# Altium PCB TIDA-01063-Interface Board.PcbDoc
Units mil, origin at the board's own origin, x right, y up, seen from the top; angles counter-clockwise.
Board outline 1968.5 x 1968.5 mil, 2 copper layers (Top Layer, Bottom Layer), stack 62 mil thick; 85 components, 32 nets, 176 pads, 89 vias.
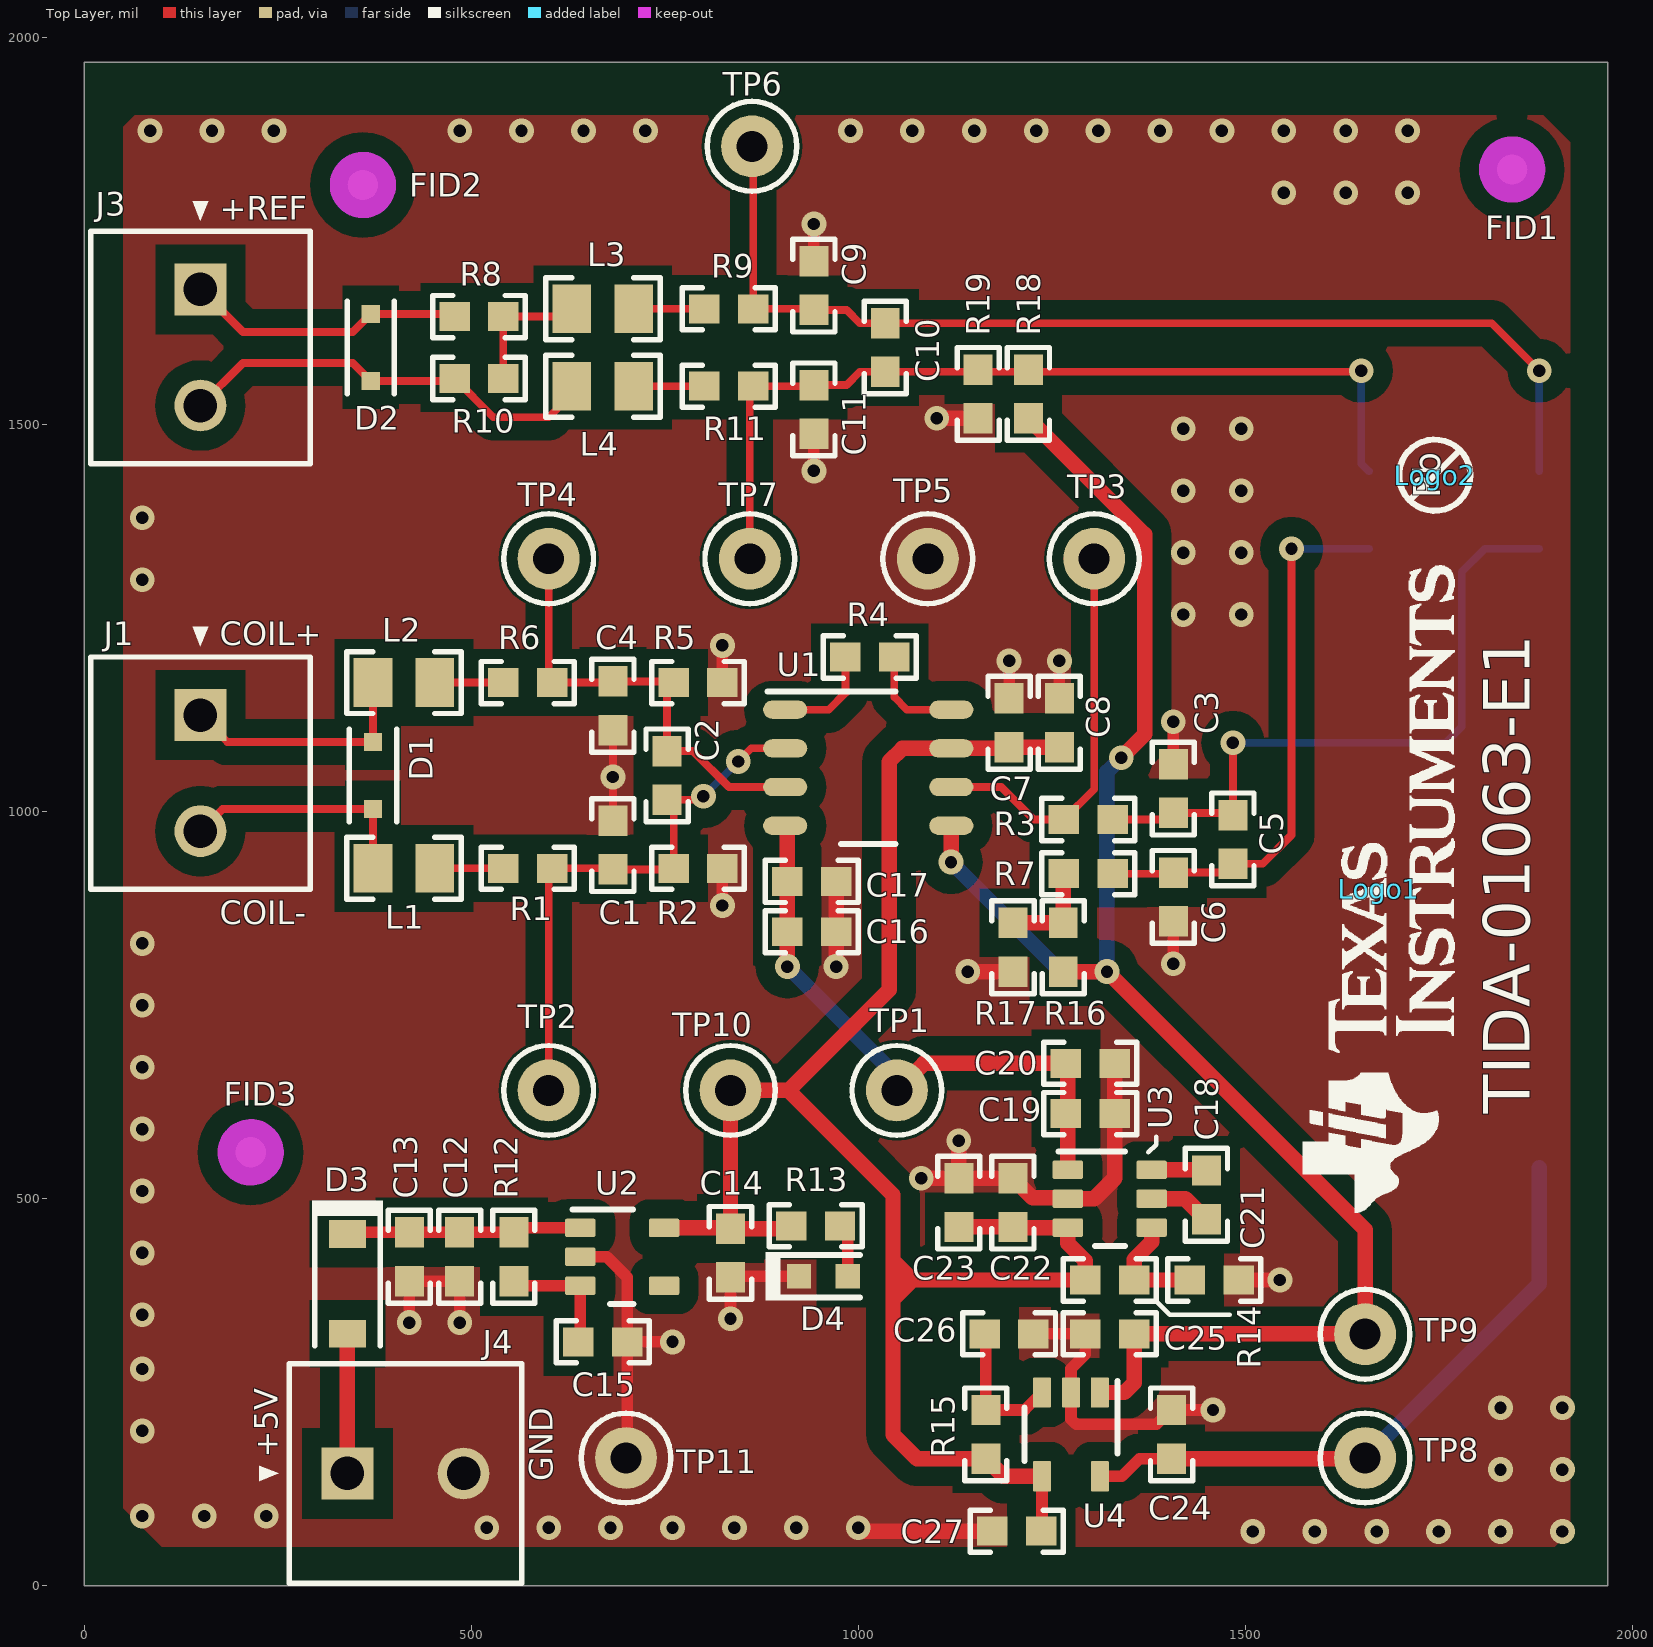
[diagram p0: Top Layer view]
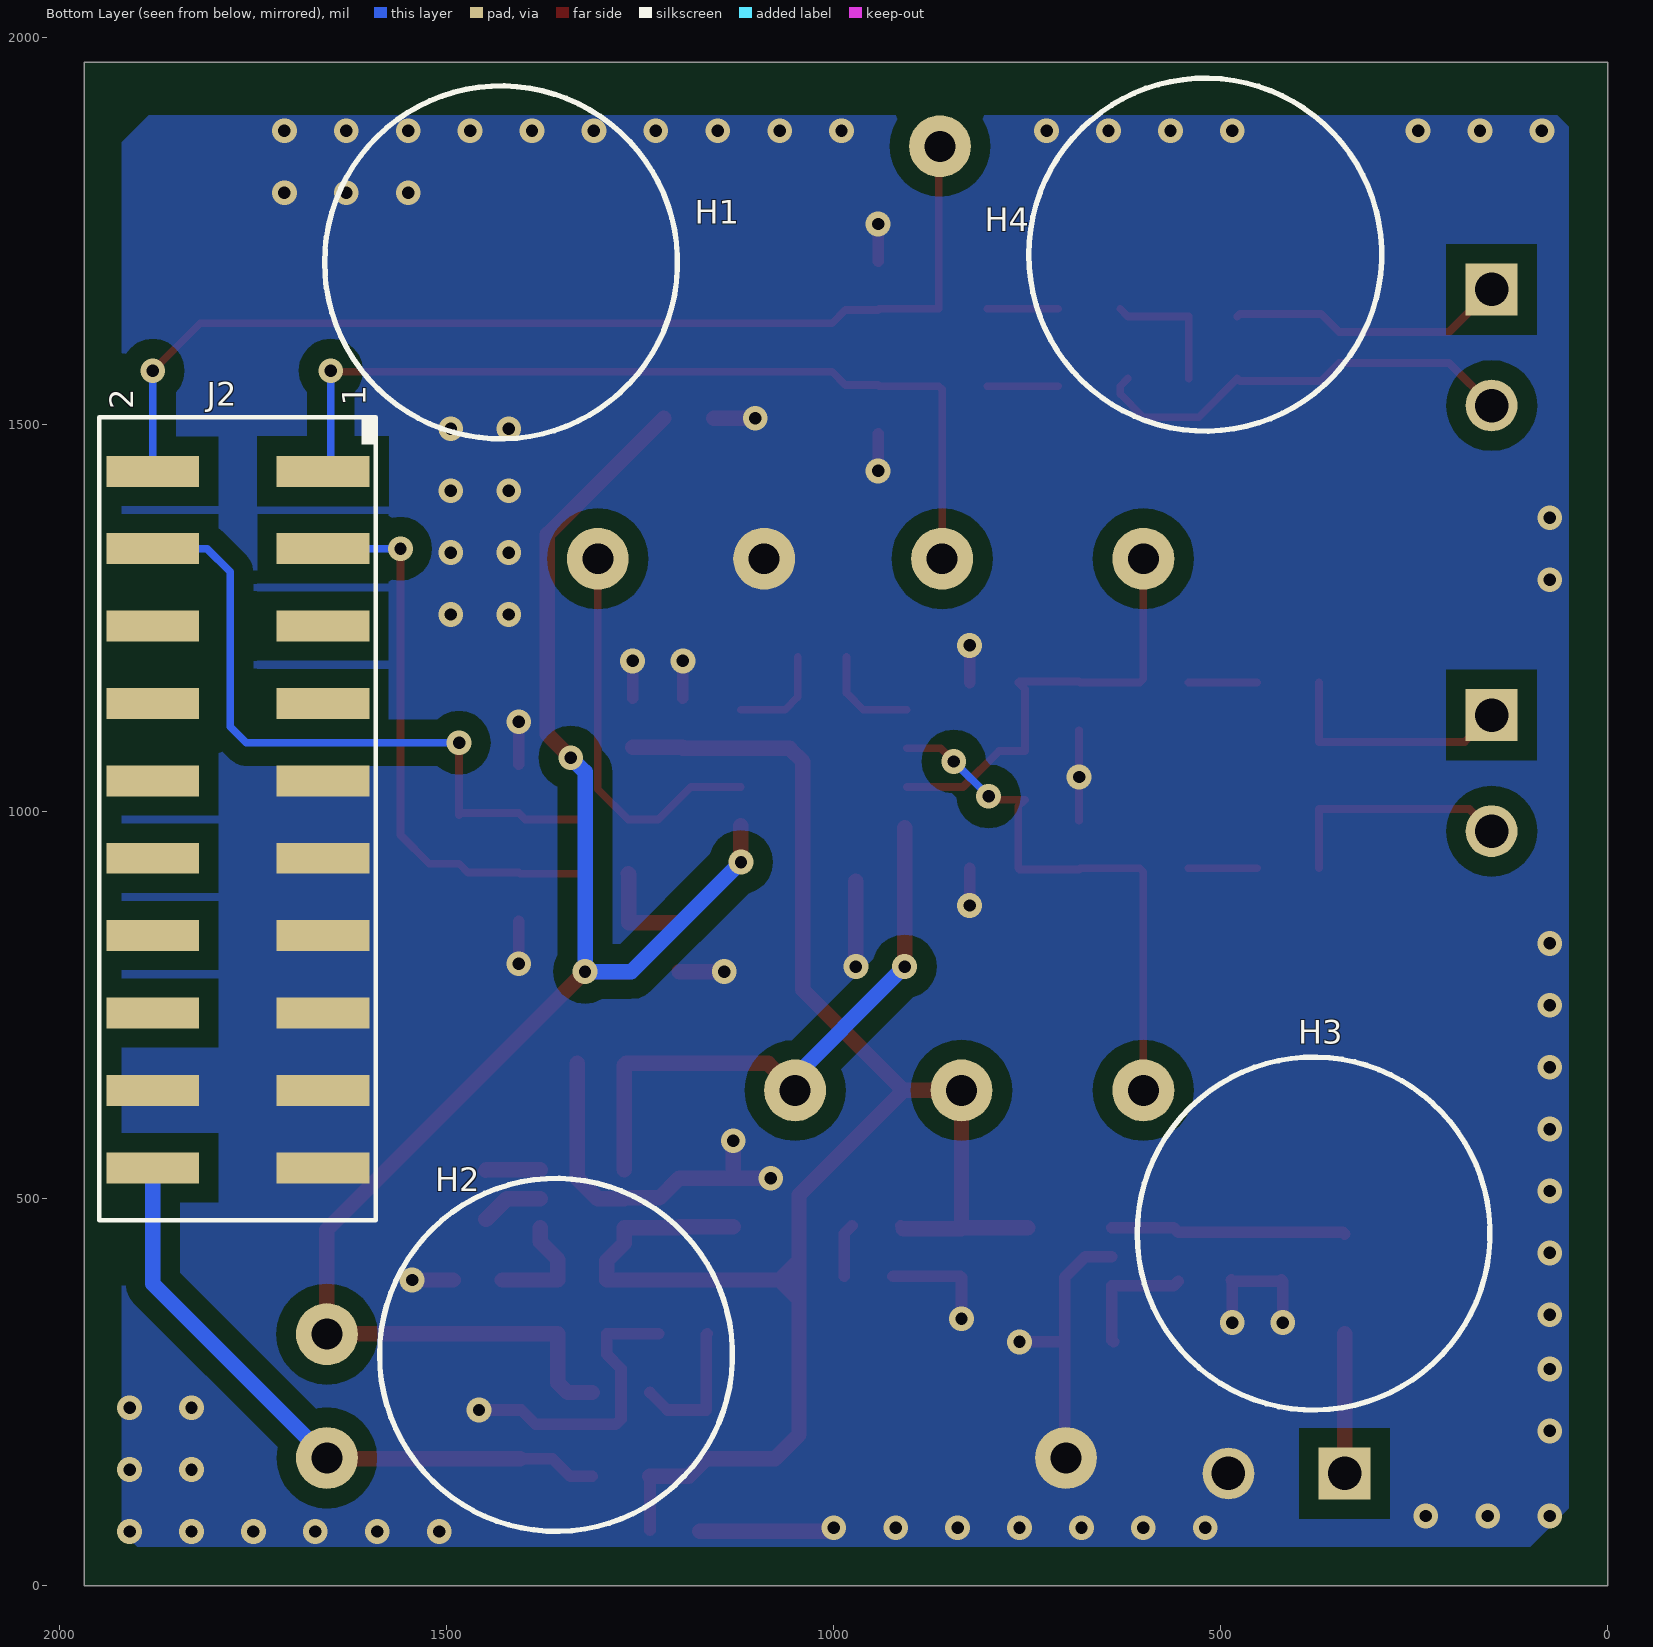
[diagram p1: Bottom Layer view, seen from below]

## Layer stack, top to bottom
Top Solder: solder mask 0.4, Solder Resist, Dk 3.5
Top Layer: signal copper 1.4
Dielectric1: core 59.2, FR-4, Dk 4.8
Bottom Layer: signal copper 1.4
Bottom Solder: solder mask 0.4, Solder Resist, Dk 3.5

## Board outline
0,0 0,1968.5 1968.5,1968.5 1968.5,0

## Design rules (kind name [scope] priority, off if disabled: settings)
AcuteAngle [All] p1: minimum=4.50000000000000E+0001 checktracksonly=FALSE
AssemblyTestPointUsage [All] p1: valid=2
Clearance Clearance_BoardEdge_MountingHoles [OnCopper and InComponentClass('Mounting Holes') vs IsKeepOut] p1: gap=40
Clearance Clearance_BoardEdge_Poly [OnCopper and InPoly vs IsKeepOut] p2: gap=25
Clearance Clearance_BoardEdge [OnCopper and Not InComponentClass('Logo') and not InComponentClass('FiducialMark') and not InRegion(1000,500,4000,800) and Not IsKeepout vs IsKeepOut] p3: gap=75
Clearance Clearance_Poly [InPolygon] p4: gap=25
Clearance [All] p5: gap=8
DiffPairsRouting [All] p1: maxlimit=100 minlimit=10 mostfreqgap=10 toplayer_minwidth=15 toplayer_maxwidth=15 toplayer_prefwidth=15 bottomlayer_minwidth=15 bottomlayer_maxwidth=15 bottomlayer_prefwidth=15 maxuncoupledlength=1000
FabricationTestPointUsage TestPointUsage [All] p1: valid=2 allowmultiple=FALSE
FabricationTestpoint Testpoint [All] p1: side=3 testpointundercomponent=TRUE minsize=40 maxsize=100 preferedsize=60 minholesize=0 maxholesize=40 preferedholesize=32 testpointgrid=1 allowsidetop=TRUE allowsidebottom=TRUE usegrid=TRUE gridtolerance=0.01
FanoutControl Fanout_LCC [IsLCC] p1: bgadir=Out bgaviamode=Centered fanoutstyle=Auto fanoutdirection=Alternating viagrid=1 // Fanout_LCC (Default Rule)
FanoutControl Fanout_BGA [IsBGA] p2: bgadir=Out bgaviamode=Centered fanoutstyle=Auto fanoutdirection=Alternating viagrid=1 // Fanout_BGA (Default Rule)
FanoutControl Fanout_Default [All] p4: bgadir=Out bgaviamode=Centered fanoutstyle=Auto fanoutdirection=Alternating viagrid=1 // Fanout_Default (Default Rule)
FanoutControl Fanout_Small [(CompPinCount < 5)] p5: bgadir=Out bgaviamode=Centered fanoutstyle=Auto fanoutdirection=OutThenIn viagrid=1 // Fanout_Small (Default Rule)
HoleSize [All] p1: absolutevalues=TRUE maxlimit=251 minlimit=8 maxpercent=80.000 minpercent=20.000
MinimumAnnularRing MinimumAnnularRing_ThermalPadVias [IsVia and InAnyComponent] p1: minimumring=5.91
MinimumAnnularRing [All] p2: minimumring=6
MinimumSolderMaskSliver MinimumSolderMaskSliver_Logo [InComponentClass('Logo') vs InComponentClass('Logo')] p1: minsoldermaskwidth=0.7
MinimumSolderMaskSliver [All] p2: minsoldermaskwidth=3.94
PlaneConnect [All] p1: planeconnectstyle=Direct reliefexpansion=10 reliefentries=4 reliefconductorwidth=10 reliefairgap=10
PolygonConnect [All] p1: connectstyle=Direct reliefconductorwidth=10 reliefentries=4 polygonreliefangle="90 Angle" airgapwidth=10
RoutingVias ThermalPadVias [IsVia and InAnyComponent] p1: holewidth=7.87 width=19.68 viastyle="Through Hole" minholewidth=7.87 minwidth=19.68 maxholewidth=12.99 maxwidth=23.62
RoutingVias [All] p2: holewidth=16 width=32 viastyle="Through Hole" minholewidth=12 minwidth=24 maxholewidth=28 maxwidth=50
SilkToBoardRegionClearance [Not ((IsComment or IsDesignator) And (Hide <> 'False')) and not InRegion(1000,500,4000,800)] p1:
SilkToSilkClearance SilkToSilkClearance_Pb-FreeLogo [(HasFootprint('Pb-Free_Overlay_Medium') OR HasFootprint('Pb-Free_Overlay_Small')) vs (HasFootprint('Pb-Free_Overlay_Medium') OR HasFootprint('Pb-Free_Overlay_Small'))] p1: silktosilkclearance=0
SilkToSilkClearance [All] p2: silktosilkclearance=4
SilkToSolderMaskClearance SilkToComonentPadClearance [IsPad and InAnycomponent] p1: minsilkscreentomaskgap=5 clearancetoexposedcopper=TRUE
SilkToSolderMaskClearance "Silk to Solder Mask Opening" [All] p2: minsilkscreentomaskgap=4 clearancetoexposedcopper=FALSE
SolderMaskExpansion [All] p1: expansion=1.97
UnpouredPolygon [All] p1: allowunpoured=FALSE
Width [All] p1: maxlimit=100 minlimit=10 preferedwidth=10 checkconnectedcopper=TRUE
15 further rules are at their usual default settings.

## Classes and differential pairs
component class AssemblyNote: ZZ1 ZZ2 ZZ3
component class FiducialMark: FID1 FID2 FID3
component class Logo: Logo1
component class TIDA-01063-BlankSheet: C1 C2 C3 C4 C5 C6 C7 C8 C9 C10 C11 C12 C13 C14 C15 C16 C17 C18 C19 C20 C21 C22 C23 C24 C25 C26 C27 D1 D2 D3 D4 J1 J2 J3 J4 L1 L2 L3 L4 R1 R2 R3 R4 R5 R6 R7 R8 R9 R10 R11 R12 R13 R14 R15 R16 R17 R18 R19 TP1 TP2 TP3 TP4 TP5 TP6 TP7 TP8 TP9 TP10 TP11 U1 U2 U3 U4
component class TIDA-01063_Hardware: !PCB1 FID1 FID2 FID3 H1 H2 H3 H4 Logo1 Logo2 ZZ1 ZZ2 ZZ3

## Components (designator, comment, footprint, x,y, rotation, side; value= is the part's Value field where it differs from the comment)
C1 "C0603X102K5RACTU" 0603 683.01,957 r270 top
C2 "06031C103JAT2A" 0603 753.01,1047 r270 top
C3 "C0805C104K1RACTU" 0603 1407.27,1030.02 r90 top
C4 "C0603X102K5RACTU" 0603 683.01,1137 r270 top
C5 "C3225X7R2A105K200AA" 0603 1484.25,964.32 r270 top
C6 "C0805C104K1RACTU" 0603 1407.27,890.02 r90 top
C7 "CGA3E2X8R1E104K080AA" 0603 1195,1115 r90 top
C8 "C1608X5R1C105K" 0603 1260,1115 r90 top
C9 "C0603X102K5RACTU" 0603 942.8,1680.02 r90 top
C10 "06031C103JAT2A" 0603 1035,1600 r270 top
C11 "C0603X102K5RACTU" 0603 942.8,1520.02 r90 top
C12 "C1608X5R1C105K" 0603 485,425 r270 top
C13 "CGA3E2X8R1E104K080AA" 0603 420,425 r270 top
C14 "C1608X5R1C105K" 0603 835,430 r270 top
C15 "CGA3E2X8R1E104K080AA" 0603 670,315 r0 top
C16 "C1608X5R1C105K" 0603 940,845 r0 top
C17 "CGA3E2X8R1E104K080AA" 0603 940,910 r0 top
C18 "C1608X5R1C105K" 0603 1450,505 r90 top
C19 "C0603C106M9PACTU" 0603 1300,610 r0 top
C20 "C0603C106M9PACTU" 0603 1300,675 r0 top
C21 "CGA3E2X8R1E104K080AA" 0603 1460,395 r0 top
C22 "C0603C106M9PACTU" 0603 1200,495 r90 top
C23 "C0603C106M9PACTU" 0603 1130,495 r90 top
C24 "CGA3E2X8R1E104K080AA" 0603 1404.96,195.5 r90 top (schematic designator C16)
C25 "CGA3E2X8R1E104K080AA" 0603 1324.96,325.5 r180 top (schematic designator C17)
C26 "CGA3E2X8R1E104K080AA" 0603 1194.96,325.5 r0 top (schematic designator C18)
C27 "CGA3E2X8R1E104K080AA" 0603 1204.96,70.5 r180 top (schematic designator C19)
D1 "CDSOD323-T03SC" SOD-323-Bi 373.01,1047 r90 top
D2 "CDSOD323-T03SC" SOD-323-Bi 370,1600 r90 top
D3 "BAT41ZFILM" SOD-123 340,390 r270 top
D4 "150060GS75000" WL-SMCW_GREEN 955,400 r0 top
FID1 "Fiducial" Fiducial10-20 1845,1830 r0 top
FID2 "Fiducial" Fiducial10-20 360,1810 r0 top
FID3 "Fiducial" Fiducial10-20 215,560 r0 top
H1 "SJ-5303 (CLEAR)" Bumpon_SJ5003Transparent 1430,1710 r180 bottom
H2 "SJ-5303 (CLEAR)" Bumpon_SJ5003Transparent 1358.96,298.23 r180 bottom
H3 "SJ-5303 (CLEAR)" Bumpon_SJ5003Transparent 380,455 r180 bottom
H4 "SJ-5303 (CLEAR)" Bumpon_SJ5003Transparent 520,1720 r180 bottom
J1 "1727010" PhoenixConact_1727010 150,1050 r270 top
J2 "SSW-110-22-F-D-VS-K" CONN_SSW-110-22-F-D-VS-K 1770,990 r90 bottom (schematic designator J?)
J3 "1727010" PhoenixConact_1727010 150,1600 r270 top
J4 "1727010" PhoenixConact_1727010 415,145 r0 top
L1 "FBMJ2125HM210NT" 0805_HV 413.01,927 r0 top
L2 "FBMJ2125HM210NT" 0805_HV 413.01,1167 r0 top
L3 "FBMJ2125HM210NT" 0805_HV 670,1650 r0 top
L4 "FBMJ2125HM210NT" 0805_HV 670,1550 r0 top
Logo1 "Texas Instruments" TI_Stacked_Overlay_Small 1672.5,900 r90 top
Logo2 "Pb-Free Symbol" Pb-Free_Overlay_Small 1745,1435 r90 top
R1 "RT0603DRE0710KL" 0603 573.01,927 r0 top
R2 "RC0603FR-07100KL" 0603 793.01,927 r0 top
R3 "CRCW06030000Z0EA" 0603 1297.27,990.02 r0 top
R4 "ERA-3AEB101V" 0603 1015,1200 r0 top
R5 "RC0603FR-07100KL" 0603 793.01,1167 r180 top
R6 "RT0603DRE0710KL" 0603 573.01,1167 r0 top
R7 "CRCW06030000Z0EA" 0603 1297.27,920.02 r0 top
R8 "RT0603DRE0710KL" 0603 510,1640 r180 top
R9 "RT0603DRE0710KL" 0603 832.8,1650.02 r0 top
R10 "RT0603DRE071KL" 0603 510,1560 r180 top
R11 "RT0603DRE0710KL" 0603 832.8,1550.02 r0 top
R12 "RC0603FR-07100KL" 0603 555,425 r90 top
R13 "RC0603FR-07390RL" 0603 945,465 r180 top
R14 "RC0603FR-07100KL" 0603 1325,395 r180 top
R15 "RC0603FR-07100KL" 0603 1164.96,195.5 r270 top (schematic designator R14)
R16 "CRCW06030000Z0EA" 0603 1265,825 r90 top
R17 "CRCW06030000Z0EA" 0603 1200,825 r270 top
R18 "CRCW06030000Z0EA" 0603 1220,1540 r90 top
R19 "CRCW06030000Z0EA" 0603 1155,1540 r270 top
TP1 "5002" Keystone5002 1050,640 r0 top
TP2 "5004" Keystone5004 600,640 r0 top
TP3 "5002" Keystone5002 1305,1327 r0 top
TP4 "5000" Keystone5000 600,1327 r0 top
TP5 "5001" Keystone5001 1090,1327 r0 top
TP6 "5000" Keystone5000 862.8,1860.02 r0 top
TP7 "5004" Keystone5004 860,1327 r0 top
TP8 "5002" Keystone5002 1655,165 r180 top
TP9 "5002" Keystone5002 1655,325 r0 top (schematic designator TP1)
TP10 "5002" Keystone5002 835,640 r180 top
TP11 "5001" Keystone5001 700,165 r0 top
U1 "INA188D" D0008A_N 1013.01,1057 r0 top
U2 "LP5907MFX-3.3/NOPB" DBV0005A_N 695,425 r0 top
U3 "LM2776DBVR" DBV0006A_N 1325,500 r0 top
U4 "REF2030AIDDCR" DDC0005A_N 1274.96,195.5 r270 top (schematic designator U3)
ZZ1 "These assemblies are ESD sensitive, ESD precautions shall be observed." AssemblyNote 5,2460 r0 top
ZZ2 "These assemblies must be clean and free from flux and all contaminants. Use of no clean flux is not acceptable." AssemblyNote 5,2370 r0 top
ZZ3 "These assemblies must comply with workmanship standards IPC-A-610 Class 2, unless otherwise specified." AssemblyNote 5,2275 r0 top

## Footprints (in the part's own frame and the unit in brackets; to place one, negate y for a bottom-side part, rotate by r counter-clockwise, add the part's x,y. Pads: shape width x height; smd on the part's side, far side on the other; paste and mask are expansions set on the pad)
0603 [mm] "0603 from SM-752 data"
  rect 1x0.95 smd: 1(-0.8,0) 2(0.8,0)
  silkscreen extent -1.52,-0.69 1.52,0.69, body extent -0.87,-0.47 0.87,0.47, height 1
0805_HV [mil] "0805 with 30mil clearance between pads"
  rect 50x63 smd: 1(-40,0) 2(40,0)
  silkscreen extent -74,-40 74,40, body extent -43,-29 43,29, height 57
AssemblyNote [mil] "Assembly Note"
Bumpon_SJ5003Transparent [mil] "3M Hemispherical Bumpon transparent"
  round 1 on Mech4: 0(0,0)
  silkscreen extent -228,-228 228,228, body extent -217,-218 219,218, height 197
CONN_SSW-110-22-F-D-VS-K [mil]
  rect 40x120 smd: 1(450,-110) 2(450,110) 3(350,-110) 4(350,110) 5(250,-110) 6(250,110) 7(150,-110) 8(150,110) 9(50,-110) 10(50,110) 11(-50,-110) 12(-50,110) 13(-150,-110) 14(-150,110) 15(-250,-110) 16(-250,110) 17(-350,-110) 18(-350,110) 19(-450,-110) 20(-450,110)
  silkscreen extent -518,-178 520,179, body extent -510,-155 500,155, height 435
D0008A_N [mm] "SOIC, 8-Leads, Body 4.9x3.9mm, Pitch 1.27mm, IPC Medium Density"
  oval 1.45x0.6 smd: 1(-2.725,1.905) 2(-2.725,0.635) 3(-2.725,-0.635) 4(-2.725,-1.905) 5(2.725,-1.905) 6(2.725,-0.635) 7(2.725,0.635) 8(2.725,1.905)
  silkscreen extent -3.3,-2.5 0.9,2.5, body extent -3,-2.45 3,2.45, height 1.63
DBV0005A_N [mm] "SOT23, 5-Leads, Body 2.9x1.6mm, Pitch 0.95mm, Lead Span 2.8mm, IPC Medium Density"
  rrect17% 1x0.6 smd: 1(-1.375,0.95) 2(-1.375,0) 3(-1.375,-0.95) 4(1.375,-0.95) 5(1.375,0.95)
  silkscreen extent -1.63,-1.55 0.38,1.55, body extent -1.42,-1.46 1.42,1.46, height 1.09
DBV0006A_N [mm] "SOT23, 6-Leads, Body 2.9x1.6mm, Pitch 0.95mm, Lead Span 2.8mm, IPC Medium Density"
  rrect17% 1x0.6 smd: 1(-1.375,0.95) 2(-1.375,0) 3(-1.375,-0.95) 4(1.375,-0.95) 5(1.375,0) 6(1.375,0.95)
  silkscreen extent -1.68,-1.55 0.5,1.55, body extent -1.42,-1.46 1.42,1.46, height 1.12
DDC0005A_N [mm]
  rrect17% 1x0.6 smd: 1(-1.375,0.95) 2(-1.375,0) 3(-1.375,-0.95) 4(1.375,-0.95) 5(1.375,0.95)
  silkscreen extent -1.75,-1.52 0.88,1.53, body extent -1.41,-1.45 1.41,1.45, height 1.1
Fiducial10-20 [mm]
  round 1 smd mask+0.5: 1(0,0)
  Top Layer keep-out circle w1.178: c0,0 r0.5
Keystone5000 [mil] "For Keystone 500x miniature loop terminals"
  round 80 hole 40: 1(0,0)
  silkscreen extent -58,-58 58,58, body extent -49,-49 49,49, height 182
Keystone5001 [mil] "For Keystone 500x miniature loop terminals"
  round 80 hole 40: 1(0,0)
  silkscreen extent -58,-58 58,58, body extent -49,-49 49,49, height 182
Keystone5002 [mil] "For Keystone 500x miniature loop terminals"
  round 80 hole 40: 1(0,0)
  silkscreen extent -58,-58 58,58, body extent -49,-49 49,49, height 182
Keystone5004 [mil] "For Keystone 500x miniature loop terminals"
  round 80 hole 40: 1(0,0)
  silkscreen extent -58,-58 58,58, body extent -49,-49 49,49, height 182
Pb-Free_Overlay_Small [mil]
  silkscreen extent -46,-46 46,46
PhoenixConact_1727010 [mm]
  rect 1.7x1.7 hole 1.1: 1(-1.905,0)
  round 1.7 hole 1.1: 2(1.905,0)
  silkscreen extent -4.8,-3.6 3.81,3.6, body extent -3.81,-3.6 3.81,3.7, height 8.52
SOD-123 [mm] "On Semi recommended land pattern"
  rect 0.915x1.22 smd: 1(-1.637,0) 2(1.637,0)
  silkscreen extent -2.74,-1.17 2.03,1.17, body extent -1.93,-0.9 1.93,0.9, height 1.35
SOD-323-Bi [mm] "SOD323, 2-Leads, Body 1.9x1.45mm, No Polarity Mark"
  rect 0.6x0.6 smd paste-0.05: 1(-1.1,0) 2(1.1,0)
  silkscreen extent -1.53,-0.77 1.53,0.77, body extent -1.27,-0.65 1.27,0.65, height 1.02
TI_Stacked_Overlay_Small [mil]
  silkscreen extent -418,-98 418,98
WL-SMCW_GREEN [mm] "WURTH"
  rect 0.8x0.8 smd: 1(-0.8,0) 2(0.8,0)
  silkscreen extent -1.9,-0.8 1.2,0.8, body extent -0.85,-0.45 0.85,0.45, height 0.8

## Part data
C1 C4 C9 C11: "CAP, CERM, 1000 pF, 50 V, +/- 10%, X7R, 0603"
C2 C10: "CAP, CERM, 0.01 µF, 100 V, +/- 5%, X7R, 0603"
C3 C6: library part C0603C104J3RACTU, "CAP, CERM, 0.1 µF, 25 V, +/- 5%, X7R, 0603"
C5: library part C1608X5R0J105K, "CAP, CERM, 1 µF, 6.3 V, +/- 10%, X5R, 0603"
C7 C13 C15 C17 C21 C24 C25 C26 C27: "CAP, CERM, 0.1 µF, 25 V, +/- 10%, X8R, AEC-Q200 Grade 0, 0603"
C8 C12 C14 C16 C18: "CAP, CERM, 1 µF, 16 V, +/- 10%, X5R, 0603"
C19 C20 C22 C23: "CAP, CERM, 10 µF, 6.3 V, +/- 20%, X5R, 0603"
D1 D2: "Diode, TVS, Bi, 3.3 V, 400 W, SOD323, 2-Leads, Body 1.9x1.45mm, No Polarity Mark"
D3: "Diode, Schottky, 100 V, 0.2 A, SOD-123"
D4: "LED, Green, SMD"
FID1 FID2 FID3: "Fiducial mark.  There is nothing to buy or mount."
H1 H2 H3 H4: "Bumpon, Hemisphere, 0.44 X 0.20, Clear"
J1 J3 J4: "Conn Term Block, 2POS, 3.81mm, TH"
J2: "Connector, Receptacle, 100mil, 10x2, Gold plated, SMD"
L1 L2 L3 L4: "Ferrite Bead, 21 ohm @ 100 MHz, 6 A, 0805"
Logo1: library part TI_Logo, "Texas Instrument Corporate Signature"
Logo2: library part Pb-Free
R1 R6 R8 R9 R11: "RES, 10.0 k, 0.5%, 0.1 W, 0603"
R2 R5 R12 R14 R15: "RES, 100 k, 1%, 0.1 W, 0603"
R3 R7 R16 R17 R18 R19: "RES, 0, 5%, 0.1 W, 0603"
R4: "RES, 100, 0.1%, 0.1 W, AEC-Q200 Grade 0, 0603"
R10: "RES, 1.00 k, 0.5%, 0.1 W, 0603"
R13: "RES, 390, 1%, 0.1 W, 0603"
TP1 TP3 TP8 TP9 TP10: "Test Point, Miniature, White, TH"
TP2 TP7: "Test Point, Miniature, Yellow, TH"
TP4 TP6: "Test Point, Miniature, Red, TH"
TP5 TP11: "Test Point, Miniature, Black, TH"
U1: "INA188 Precision, Zero-Drift, Rail-to-Rail Out, High Voltage Instrumentation Amplifier, D0008A"
U2: "ULTRA LOW-NOISE, 250-mA LINEAR REGULATOR FOR RF AND ANALOG CIRCUITS REQUIRES NO BYPASS CAPACITOR, DBV0005A"
U3: "Switched Capacitor Inverter, DBV0006A"
U4: "Low-Drift, Low-Power, Dual-Output, VREF and VREF / 2 Voltage References, 3.0V, DDC0005A"
ZZ1 ZZ2 ZZ3: library part AssemblyNote

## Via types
v1: diameter 32, hole 16, Top Layer to Bottom Layer, 89 vias

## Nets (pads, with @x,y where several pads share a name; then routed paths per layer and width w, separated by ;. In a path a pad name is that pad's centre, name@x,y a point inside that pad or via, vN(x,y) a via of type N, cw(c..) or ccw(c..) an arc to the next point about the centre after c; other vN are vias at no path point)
+3.3V: C7.1 C8.1 C14.1 C22.1 C23.1 C27.1 R13.2 R14.2 R15.2 TP10.1 U1.7 U2.5 U3.3 U4.4 | length 2447.9
  Top Layer w15: R13.2@910,461.5 R13.2 ; C27.1@1237.56,71.6 U4.4
  Top Layer w20: U2.5 C14.1@834.09,462.4 ; R13.2@910,461.5 C14.1 C14.1@834.09,462.4 ; 1045,370 1070,395 1045,420 ; C23.1 C22.1 1200.91,462.6 U3.3 1270.87,442.33 1293.5,419.7 R14.2 1045,395 ; C7.1@1195,1082 U1.7 1057,1082 1040,1065 1040,770 910,640 ; C7.1 C8.1 ; U4.4 1187.6,141.37 R15.2 1076,164 1045,195 1045,395 ; C14.1@834.09,462.4 835,463.31 TP10.1 910,640 ; 910,640 1045,505 1045,395
-3.3V: C16.1 C17.1 C19.1 C20.1 TP1.1 U1.4 U3.1 | length 777.1
  Top Layer w20: v1(908.5,800) C16.1 C17.1 U1.4@908.5,979.23 ; TP1.1 1085,675 C20.1 1270.87,672.64 U3.1
  Bottom Layer w20: v1(908.5,800) TP1.1@1068.5,640
AN0+: C9.1 C10.1 J2.2 R9.2 TP6.1 | length 1389.5
  Top Layer w10: TP6.1 864.3,1858.52 R9.2 941.3,1650.02 C9.1 985,1648.52 1002.03,1631.5 C10.1 1818.5,1631.5 v1(1880,1570)
  Bottom Layer w10: J2.2 v1(1880,1570)
AN0-: C10.2 C11.2 J2.1 R11.2 R18.2 R19.1 TP7.1 | length 1779.3
  Top Layer w10: TP7.1 860,1545.72 R11.2 941.3,1550.02 C11.2 985,1551.51 1001.99,1568.5 C10.2 1648.5,1568.5 C10.2@1022.8,1568.52 ; TP7.1@864.3,1324.3 TP7.1@864.3,1327
  Bottom Layer w10: v1(1650,1570) 1650,1450 J2.1
AN1+: C3.1 C5.1 J2.4 R3.2 | length 870.4
  Top Layer w10: R3.2 1398.76,990.02 C3.1 1481.54,998.52 C5.1 v1(1484.25,1089.32)
  Bottom Layer w10: v1(1484.25,1089.32) 1759.32,1089.32 1780,1110 1780,1310 1810,1340 J2.4
AN1-: C5.2 C6.2 J2.3 R7.2 | length 721.9
  Top Layer w10: R7.2 1405.77,920.02 C6.2 1472.95,921.51 C5.2 1522.76,932.82 1560,970.06 v1(1560,1340)
  Bottom Layer w10: v1(1560,1340) J2.3
GND: C1.1 C3.2 C4.2 C6.1 C7.2 C8.2 C9.2 C11.1 C12.2 C13.2 C14.2 C15.2 C16.2 C17.2 C19.2 C20.2 C21.2 C22.2 C23.2 C24.2 C25.2 C26.2 C27.2 D4.1 J2.9 J2.11 J2.13 J2.15 J2.17 J2.18 J2.19 J4.2 R2.2 R5.1 R17.2 R19.2 TP5.1 TP11.1 U2.2 U3.2 U4.2 | length 2496.1
  Top Layer w10: C1.1 v1(683.01,1045) C4.2
  Top Layer w15: v1(420,340) C13.2 ; C13.2@421.5,395 C13.2 ; v1(485,340) C12.2 ; C12.2@486.5,395 C12.2 ; U2.2 675,425 701.5,398.5 C15.2 ; TP11.1@701.5,166.5 C15.2 ; v1(760,315) C15.2 ; v1(824.51,879) R2.2 ; R5.1 v1(824.51,1215) ; v1(835,345) C14.2 836.5,400 D4.1 ; v1(942.8,1440.52) C11.1 ; C9.2 v1(942.8,1759.51) ; C7.2 v1(1195,1195) ; C26.2 C25.2 1293.46,299 1274.96,280.5 U4.2 1274.96,215.19 1281.78,208.37 1385.48,208.37 1404.11,227 C24.2 v1(1458.46,227) ; C8.2 v1(1260,1195) ; v1(1407.27,803.73) C6.1 ; C3.2 v1(1407.27,1116.3) ; C13.2 C12.2
  Top Layer w20: v1(971.5,800) C16.2 C17.2 ; v1(1000,75) 1004.5,70.5 C27.2 ; v1(1081.5,526.5) C23.2 ; v1(1101.5,1508.5) R19.2 ; v1(1130,575) C23.2 ; v1(1141.5,793.5) R17.2 ; C20.2 C19.2 1331.5,526.5 1305,500 U3.2 1270.87,501.19 1225.31,501.19 C22.2 C23.2 ; C21.2 v1(1545,395)
  other v1: 1510,70 1590,70 1670,70 1750,70 1830,70 1910,70 520,75 600,75 680,75 760,75 840,75 920,75 75,90 155,90 235,90 1830,150 1910,150 75,200 1830,230 1910,230 75,280 75,350 75,430 75,510 75,590 75,670 75,750 75,830 1420,1255 1495,1255 75,1300 1420,1335 1495,1335 75,1380 1420,1415 1495,1415 1420,1495 1495,1495 1550,1800 1630,1800 1710,1800 85,1880 165,1880 245,1880 485,1880 565,1880 645,1880 725,1880 990,1880 1070,1880 1150,1880 1230,1880 1310,1880 1390,1880 1470,1880 1550,1880 1630,1880 1710,1880
NetC1_2: C1.2 C2.2 R1.2 R2.1 TP2.1 U1.2 | length 719.4
  Top Layer w10: TP2.1 600,922.49 R1.2 681.52,927 C1.2 760.02,925.5 R2.1 761.52,1007 C2.2 795.5,1015.5 v1(800,1020) ; v1(845,1065) 862,1082 U1.2
  Bottom Layer w10: v1(800,1020) v1(845,1065)
NetC2_1: C2.1 C4.1 R5.2 R6.2 TP4.1 U1.3 | length 584.1
  Top Layer w10: TP4.1 600,1171.51 R6.2 681.52,1167 C4.1 760.02,1168.5 R5.2 753.01,1158.5 C2.1 786.5,1078.5 833,1032 U1.3
NetC12_1: C12.1 C13.1 D3.1 R12.2 U2.1 | length 304.2
  Top Layer w15: D3.1 342.03,456.5 C13.1 C12.1 R12.2 560.91,462.4 U2.1
NetC15_1: C15.1 R12.1 U2.3 | length 161.9
  Top Layer w15: R12.1 560.91,387.6 U2.3 640.87,317.36 C15.1
NetC18_1: C18.1 U3.5 | length 81.8
  Top Layer w20: U3.5 1422.65,500 1449.15,473.5 C18.1
NetC18_2: C18.2 U3.6 | length 71.2
  Top Layer w20: U3.6 1449.09,537.4 C18.2
NetC21_1: C21.1 R14.1 U3.4 | length 149
  Top Layer w20: U3.4 1379.13,444.13 1356.5,421.5 R14.1 C21.1
NetC26_1: C26.1 R15.1 U4.3 | length 181.1
  Top Layer w15: C26.1 1164.96,324 R15.1 1214.92,227 U4.3
NetD1_1: D1.1 J1.2 L1.1 | length 330.1
  Top Layer w10: J1.2@150,965 165,965 J1.2@167.5,967.5 ; J1.2 178.69,1003.69 D1.1 L1.1
NetD1_2: D1.2 J1.1 L2.1 | length 321.1
  Top Layer w10: J1.1 184.69,1090.31 D1.2 L2.1 ; J1.1@150,1135 J1.1@155,1130
NetD2_1: D2.1 J3.2 L4.1 R10.2 | length 571.1
  Top Layer w10: J3.2 205,1580 346.69,1580 D2.1 475.2,1556.69 R10.2 528.5,1510 600,1510 630,1540 L4.1 L4.1@620,1560
NetD2_2: D2.2 J3.1 R8.2 | length 362.3
  Top Layer w10: J3.1 205,1620 346.69,1620 D2.2 475.2,1643.31 R8.2
NetD3_2: D3.2 J4.1 | length 180.5
  Top Layer w20: J4.1 D3.2
NetD4_2: D4.2 R13.1 | length 69.1
  Top Layer w15: R13.1 986.5,455 D4.2
NetL1_2: L1.2 R1.1 | length 88.5
  Top Layer w10: L1.2 R1.1
NetL2_2: L2.2 R6.1 | length 88.5
  Top Layer w10: L2.2 R6.1
NetL3_1: L3.1 R8.1 R10.1 | length 172.6
  Top Layer w10: R10.1 R8.1 620,1640 L3.1
NetL3_2: L3.2 R9.1 | length 91.3
  Top Layer w10: L3.2 R9.1
NetL4_2: L4.2 R11.1 | length 91.3
  Top Layer w10: L4.2 R11.1
NetR4_1: R4.1 U1.1 | length 133.2
  Top Layer w10: U1.1 962,1132 983.5,1153.5 R4.1
NetR4_2: R4.2 U1.8 | length 132.1
  Top Layer w10: R4.2 1046.5,1148.5 1063,1132 U1.8
NetR7_1: R7.1 R16.2 R17.1 | length 128.8
  Top Layer w20: R17.1 R16.2 1265,919.25 R7.1
VBIAS: C25.1 R16.1 R18.1 TP9.1 U1.5 U4.1 | length 2178.4
  Top Layer w20: v1(1120,935) 1120.3,935.3 U1.5 ; R18.1 1370,1358.5 1370,1100 v1(1340,1070) ; R16.1 v1(1321.5,793.5) 1655,460 TP9.1 ; U4.1 1344.09,249.63 1356.46,262 C25.1 TP9.1@1654.5,325.5
  Bottom Layer w20: v1(1120,935) 1261.5,793.5 v1(1321.5,793.5) 1321.5,1051.5 v1(1340,1070)
VIN: R3.1 TP3.1 U1.6 | length 518.2
  Top Layer w10: U1.6 1185,1032 1226.98,990.02 R3.1 1305,1029.25 TP3.1 ; TP3.1@1270,1327 TP3.1@1271.52,1325.48
VREF: C24.1 J2.20 TP8.1 U4.5 | length 820.6
  Top Layer w15: U4.5 1340.83,141.37 1363.46,164 C24.1
  Top Layer w20: C24.1 1654,164 TP8.1
  Bottom Layer w20: TP8.1 1880,390 J2.20
pads on no net: FID1.1 FID2.1 FID3.1 H1.0 H2.0 H3.0 H4.0 J2.5 J2.6 J2.7 J2.8 J2.10 J2.12 J2.14 J2.16 U2.4

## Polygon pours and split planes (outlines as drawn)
GND on Bottom Layer "Bottom Layer-No Net 1" (solid, remove dead copper, pour order 4): 50,1885 50,100 100,50 1900,50 1920,70 1920,130 1920,1865 1885,1900 65,1900
GND on Top Layer "Bottom Layer-No Net 1" (solid, remove dead copper, pour order 3): 50,1885 50,100 100,50 1900,50 1920,70 1920,130 1920,1865 1885,1900 65,1900

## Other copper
Top Layer:
  text "Top Layer" at -1381,-4374.49 h60
Bottom Layer:
  text ".Layer_Name" at -1381,-4374.49 h60

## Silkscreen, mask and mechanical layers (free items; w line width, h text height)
Top Overlay:
  lines w6: 1375,560 1385,570 1385,580 ; 1384.98,367.73 1402.72,350 1480,350
  text "+REF" at 175,1765 h30
  text "COIL+" at 175,1215 h30
  text "COIL-" at 175,855 h30
  text "TIDA-01063-E1" at 1867.5,610 h60 r90
  text "+5V" at 250,165 h30 r90
  text "GND" at 605,135 h30 r90
  text "TOP Overlay" at -1381,-4374.49 h60
Bottom Overlay:
  text ".Layer_Name" at -1381,-4374.49 h60
Top Paste:
  text ".Layer_Name" at -1381,-4374.49 h60
Bottom Paste:
  text ".Layer_Name" at -1381,-4374.49 h60
Top Solder:
  text ".Layer_Name" at -1381,-4374.49 h60
  text ".Layer_Name" at -1381,-4374.49 h60
Bottom Solder:
  text ".Layer_Name" at -1381,-4374.49 h60
M1 Board Outline:
  the board outline again, w7
M2 Board Dimensions:
  rectangle: -1833,-3916 -1458,-3791
  rectangle: -1958,-3791 -1833,-3666
  lines w7: -1958,-3791 -958,-3791 ; -1833,-3916 -1833,-3666 ; -1708,-3916 -1708,-3666 ; -1458,-3916 -1458,-3666 ; -1208,-3916 -1208,-3666 ; -1958,-3916 -1958,-3666 -958,-3666 -958,-3916 -1958,-3916
M3 3D STEP Top:
  text ".Layer_Name" at -1381,-4374.49 h60
M4 3D STEP Bottom:
  text ".Layer_Name" at -1381,-4374.49 h60
M5 Assembly Top:
  circle w10: c1310,215 r5
  circle w10: c615,462.4 r12.44
  lines w10: -2250,-4446.17 4350,-4446.17 ; -2250,-4242.83 4352,-4242.83 ; -2250,-4039.5 -2250,-4649.5 1755,-4649.5 4352,-4649.5 4352,-4039.5 -2249.5,-4039.5 -2249.5,-4649.5 -674,-4649.5 ; 215,-4649.5 215,-4039.5 ; 1482,-4242.83 1482,-4039.5 ; 2322,-4242.83 2322,-4039.5 ; 2944,-4656 2944,-4453.17
  text "COMPONENTS MARKED 'DNP' SHOULD NOT BE POPULATED." at -804.5,-3834.5 h30
  text "ASSEMBLY VARIANT:" at -805,-3950 h30
  text ".VariantName" at 231,-3950 h30
  text "PCB VIEWED FROM TOP SIDE" at -2186.5,-4171.67 h30
  text "BOARD #:" at 290,-4171.67 h30
  text ".PRJ_Number" at 835.5,-4171.67 h30
  text "REV:" at 1680,-4171.67 h30
  text ".PCB_Rev" at 1971.5,-4171.67 h30
  text "SVN REV:" at 2518,-4171.67 h30
  text ".VersionControl_RevNumber" at 3024,-4171.67 h30
  text "M5 Assembly Top" at -1360,-4365 h30
  text "TIDA-01063" at 740,-4370 h30
  text "LAYER NAME =" at -2183.5,-4373.49 h30
  text "TID #:" at 290,-4375 h30
  text "PLOT NAME =" at -2186.5,-4580.34 h30
  text ".plot_File_Name" at -1381,-4580.34 h30
  text "GENERATED    :" at 292,-4580.34 h30
  text ".Print_Date" at 1161.5,-4580.34 h30
  text ".Print_Time" at 1890.5,-4580.34 h30
  text "TEXAS INSTRUMENTS" at 3155,-4580.34 h30
M6 Assembly Bottom:
  lines w10: -2250.5,-4243.33 4351.5,-4243.33 ; -2248.5,-4446.67 4351.5,-4446.67 ; -842.5,-4656.5 -842.5,-4453.67 ; -220.5,-4243.33 -220.5,-4040 ; 619.5,-4243.33 619.5,-4040 ; 1886.5,-4650 1886.5,-4040 ; 2775.5,-4650 4351,-4650 4351,-4040 -2250.5,-4040 -2250.5,-4650 346.5,-4650 4351.5,-4650 4351.5,-4040
  text "COMPONENTS MARKED 'DNP' SHOULD NOT BE POPULATED." at 4144,-3834 h30
  text ".VariantName" at 3100,-3950 h30
  text "ASSEMBLY VARIANT:" at 4139,-3950 h30
  text ".VersionControl_RevNumber" at -922.5,-4172.17 h30
  text "SVN REV:" at -416.5,-4172.17 h30
  text ".PCB_Rev" at 130,-4172.17 h30
  text "REV:" at 421.5,-4172.17 h30
  text ".PRJ_Number" at 1266,-4172.17 h30
  text "BOARD #:" at 1811.5,-4172.17 h30
  text "PCB VIEWED FROM BOTTOM SIDE" at 4288,-4172.17 h30
  text "M6 Assembly Bottom" at 3455,-4370 h30
  text "TIDA-01063" at 1266,-4375.5 h30
  text "TID #:" at 1811.5,-4375.5 h30
  text "LAYER NAME =" at 4278.5,-4378.49 h30
  text "TEXAS INSTRUMENTS" at -1053.5,-4580.84 h30
  text ".Print_Time" at 211,-4580.84 h30
  text ".Print_Date" at 940,-4580.84 h30
  text "GENERATED    :" at 1809.5,-4580.84 h30
  text ".plot_File_Name" at 3482.5,-4580.84 h30
  text "PLOT NAME =" at 4288,-4580.84 h30
M9 Title Sheet:
  drawing of 58 lines, arcs and shapes, not listed
  text "1" at -1218.16,4520.5 h70
  text "2" at 1277.5,4520.5 h70
  text "3" at 3766.84,4520.5 h70
  text "4" at 6273.51,4520.5 h70
  text "5" at 8772.5,4520.5 h70
  text "6" at 11277.5,4520.5 h70
  text "A" at -2374.5,3377.5 h70
  text "A" at 12425.5,3377.5 h70
  text "B" at -2374.5,997.5 h70
  text "B" at 12425.5,997.5 h70
  text "C" at -2374.5,-1377.5 h70
  text "C" at 12425.5,-1377.5 h70
  text "PROJECT TITLE:" at 9385.5,-3238.5 h45
  text "TIDA-01063" at 9435.5,-3371.83 h70
  text "DESIGNED FOR:" at 9385.5,-3539.5 h45
  text "Current Sensing using PCB Rogowski Coil" at 9435.5,-3679.5 h70
  text "D" at -2374.5,-3747.5 h70
  text "D" at 12425.5,-3747.5 h70
  text "FILE NAME:" at 9385.5,-3839.5 h45
  text "TIDA-01063-Interface Board" at 9435.5,-3959.5 h70
  text "Texas Instruments (TI) and/or its licensors do not warrant the accuracy or completeness of this specification" at 4416,-4121.34 h45
  text "ENGINEER:" at 9385.5,-4129.5 h45
  text "LAYOUT BY:" at 10890.5,-4129.5 h45
  text "or any information contained therein. TI and/or its licensors do not warrant that this design will meet" at 4371.01,-4234 h45
  text "Srinivasan Iyer" at 9435.5,-4284.49 h70
  text "Avinash N" at 10941,-4284.49 h70
  text "the specifications, will be suitable for your application or fit for any particular purpose, or will operate in" at 4371.01,-4346.67 h45
  text "ALTIUM DESIGNER VERSION:" at 10890.5,-4439.5 h45
  text "an implementation. TI and/or its licensors do not warrant that the design is production worthy. You should" at 4371.01,-4459.33 h45
  text "completely validate and test your design implementation to confirm the system functionality for your application." at 4416,-4572 h45
  text ".print_Scale" at 9435.5,-4572.83 h70
  text ".Application_BuildNumber" at 10941,-4572.83 h70
  text "1" at -1218.16,-4779.5 h70
  text "2" at 1277.5,-4779.5 h70
  text "3" at 3766.84,-4779.5 h70
  text "4" at 6273.51,-4779.5 h70
  text "5" at 8772.5,-4779.5 h70
  text "6" at 11277.5,-4779.5 h70
M10 Fab Notes:
  drawing of 228 lines, arcs and shapes, not listed
  text "DESIGN INFORMATION" at 10423.02,3294 h60
  text "(REFER ALSO ARRAY/PANEL PROFILING INFORMATION)" at 10061.46,3132.29 h60
  text "BOARD SIZE" at 9375.46,3128 h60
  text "50MM" at 9837.78,3000.18 h60
  text "X" at 10343.46,3000.18 h60
  text "50MM" at 10574.78,3000.18 h60
  text "Number of Layers :" at 9778.46,2803 h60
  text "2" at 10873.27,2793 h60
  text "MIN. TRACK WIDTH:" at 9778.46,2664 h60
  text "10" at 10874.7,2664 h60
  text "MIL" at 11029.46,2664 h60
  text "8.9" at 10833.1,2548.82 h60
  text "MIN. CLEARANCE:" at 9778.46,2532 h60
  text "MIL" at 11029.46,2532 h60
  text "16" at 10845.28,2408.9 h60
  text "MIN. VIA DRILL SIZE:" at 9778.46,2400 h60
  text "MIL" at 11029.46,2400 h60
  text "8 MIL" at 10473.46,2258.29 h60
  text "MINIMUM ANNULAR RING" at 9449.23,2254 h60
  text "EXTERNAL" at 11181.46,2254 h60
  text "PER" at 9649.23,2136 h60
  text "IPC-D-275 CLASS 2 LEVEL C" at 9869.23,2136 h60
  text "MIL, HOLES" at 11357.46,2023.71 h60
  text "+/-" at 10965,2023 h60
  text "+/-" at 11819,2023 h60
  text "REGISTRATION TOLERANCES:" at 9449.23,2018 h60
  text "METAL" at 10649,2018 h60
  text "5" at 11225.2,2018 h60
  text "3" at 12058.2,2018 h60
  text "MIL" at 12174.46,2018 h60
  text "MATERIAL:" at 9374.46,1808.54 h60
  text "FR-4 High Tg" at 10360.9,1668.21 h60
  text "FR-408" at 9795.46,1659.64 h60
  text "X" at 10202,1660 h60
  text "OTHER" at 11283.46,1659.64 h60
  text "63 MIL (1.6mm) +/-10%" at 10115.56,1496.92 h60
  text "THICKNESS:" at 9449.23,1492.64 h60
  text "X" at 9987.4,1492.64 h60
  text "OTHER" at 11400.46,1492.64 h60
  text "TOLERANCE:" at 9449.23,1334.64 h60
  text "X" at 10288.53,1334.64 h60
  text "ANSI IPC-6012 TYPE 3 CLASS 2" at 10475.48,1334.64 h60
  text "OTHER +/-" at 10475.46,1178.64 h60
  text "BOW & TWIST:" at 9449.23,1021.64 h60
  text "X" at 10288.53,1021.64 h60
  text "ANSI IPC-6012 TYPE 3 CLASS 2" at 10475.48,1021.64 h60
  text "OTHER +/-" at 10475.46,863.13 h60
  text "COPPER THICKNESS (FINISHED):" at 9374.46,727.64 h60
  text "1.4MIL (1oz)" at 10254.46,574.92 h60
  text "2MIL (1.4oz)" at 11021.46,574.92 h60
  text "2.8MIL (2oz)" at 11748.46,574.92 h60
  text "OUTER:" at 9731.46,570.64 h60
  text "X" at 10126,570 h60
  text "1.4MIL (1oz)" at 10254.46,417.92 h60
  text "2.8MIL (2oz)" at 11021.46,417.92 h60
  text "N/A" at 11748,418.29 h60
  text "INNER SIGNAL:" at 9442.38,413.64 h60
  text "X" at 11621,410 h60
  text "DRILLING:" at 9374.46,274.64 h60
  text "REFERENCE:" at 9449.23,157.64 h60
  text "X" at 10097.46,157.64 h60
  text "AS SHOWN" at 10284.46,157.64 h60
  text "X" at 10998.46,157.64 h60
  text "NC_DRILL FILES" at 11135.46,157.64 h60
  text "PTH MIN COPPER THICKNESS:" at 9449.23,-0.36 h60
  text "X" at 10799.46,-0.36 h60
  text "1MIL" at 10936.46,-0.36 h60
  text "OTHER" at 11433.46,-0.36 h60
  text "BOARD FINISH:" at 9374.46,-159.36 h60
  text "SILKSCREEN:" at 9529.68,-277.36 h60
  text "X" at 10478.46,-277.36 h60
  text "TOP" at 10604.46,-277.36 h60
  text "X" at 10988.46,-277.36 h60
  text "BOTTOM" at 11115.46,-277.36 h60
  text "SILKSCREEN COLOR:" at 9529.68,-444.36 h60
  text "X" at 10477.42,-444.36 h60
  text "WHITE" at 10604.46,-444.36 h60
  text "OTHER" at 11115.46,-444.36 h60
  text "SOLDER RESIST COLOR:" at 9529.68,-614.36 h60
  text "X" at 10097.42,-773.56 h60
  text "GREEN" at 10224.46,-773.56 h60
  text "BLUE" at 10815.46,-773.56 h60
  text "OTHER" at 11353.46,-773.56 h60
  text "IMMERSION GOLD (ENIG)" at 10435.46,-962.08 h60
  text "ENEPIG" at 11773,-965.36 h60
  text "SURFACE FINISH:" at 9374.46,-966.36 h60
  text "X" at 10248.51,-966.36 h60
  text "IMM. TIN/SILVER OR EQUIV" at 9704,-1123.36 h60
  text "OTHER" at 11135.46,-1123.36 h60
  text "ARRAY/PANEL:" at 9374.46,-1302.36 h60
  text "CUT AND TRIM PER MECH LAYER 1" at 10435.46,-1306.65 h60
  text "N.C. ROUTE" at 10435.46,-1458.36 h60
  text "X" at 11114.46,-1458.36 h60
  text "V. SCORE" at 11301.46,-1458.36 h60
  text "CERTIFICATION:" at 9374.46,-1595.36 h60
  text "MATERIALS AND WORKMANSHIP FOR ALL PCBS" at 10099.46,-1595.36 h60
  text "TO MEET OR EXCEED THE REQUIREMENTS OF:" at 10099.46,-1693.36 h60
  text "X" at 9725.96,-1829.87 h60
  text "ANSI IPC-A-600F CLASS ->" at 9864.96,-1829.87 h60
  text "X" at 11504.02,-1829.87 h60
  text "2" at 11622.96,-1829.86 h60
  text "1" at 11307.96,-1831.36 h60
  text "3" at 11976.96,-1831.36 h60
  text "X" at 9728.02,-1989.36 h60
  text "UL 94V-0" at 9864.96,-1989.36 h60
  text "X" at 10540.02,-1989.36 h60
  text "RoHS" at 10676.96,-1989.36 h60
  text "OTHER" at 11321.36,-1989.36 h60
  text "PER ORDER" at 11718.42,-1989.36 h60
  text "X" at 11670.28,-2121.1 h60
  text "VIA TENTING:" at 10592,-2123 h60
  text "ADDITIONAL REQUIREMENTS:" at 9374.46,-2130.36 h60
  text "YES" at 11141.67,-2132.08 h60
  text "NO" at 11506.47,-2137.31 h60
  text "MICROSECTION:" at 9449.23,-2245.36 h60
  text "YES" at 10354.96,-2245.36 h60
  text "IMPEDANCE CONTROL:" at 10614,-2252 h60
  text "YES" at 11598,-2253 h60
  text "X" at 12140,-2260 h60
  text "NO" at 11973.47,-2270.31 h60
  text "REQUIRED" at 11216.46,-2401.51 h60
  text "BARE BOARD ELEC. TEST:" at 9449.23,-2404.36 h60
  text "NONE" at 10754.96,-2404.36 h60
  text "X" at 11089.46,-2404.36 h60
  text "PER ORDER" at 11808.46,-2404.36 h60
  text "MANUFACTURER'S UL:" at 9449.23,-2561.36 h60
  text "RAIL" at 10614.96,-2565.65 h60
  text "METAL" at 11106.77,-2565.65 h60
  text "X" at 11482,-2566 h60
  text "SILK" at 11618.46,-2565.65 h60
M11 Gerber Information:
  lines w10: -2250,-4446.17 4350,-4446.17 ; -2250,-4242.83 4352,-4242.83 ; -2250,-4039.5 -2250,-4649.5 1755,-4649.5 4352,-4649.5 4352,-4039.5 -2249.5,-4039.5 -2249.5,-4649.5 -674,-4649.5 ; 215,-4649.5 215,-4039.5 ; 1482,-4242.83 1482,-4039.5 ; 2322,-4242.83 2322,-4039.5 ; 2944,-4656 2944,-4453.17
  text "ALL ARTWORK VIEWED FROM TOP SIDE" at -2186.5,-4171.67 h60
  text "BOARD #:" at 290,-4171.67 h60
  text "TIDA-01063" at 835.5,-4171.67 h60
  text "REV:" at 1680,-4171.67 h60
  text "E1" at 1971.5,-4171.67 h60
  text "SVN REV:" at 2518,-4171.67 h60
  text ".VersionControl_RevNumber" at 3024,-4171.67 h60
  text "LAYER NAME =" at -2186.5,-4374.49 h60
  text "TID #:" at 290,-4375 h60
  text "TIDA-01063" at 835.5,-4375 h60
  text ".plot_File_Name" at -1510,-4575 h40
  text "PLOT NAME =" at -2186.5,-4580.34 h60
  text "GENERATED    :" at 292,-4580.34 h60
  text ".Print_Date" at 1161.5,-4580.34 h60
  text ".Print_Time" at 1890.5,-4580.34 h60
  text "TEXAS INSTRUMENTS" at 3155,-4580.34 h60
M12 Stackup:
  lines w6: 9372,4047 11922,4047 ; 9372,4151.4 11922,4151.4 ; 9312,3562 ccw(c9346,3562) 9346,3528 11948,3528 ccw(c11948,3562) 11982,3562 11982,4268 ccw(c11948,4268) 11948,4302 9346,4302 ccw(c9346,4268) 9312,4268 9312,3562
  text "Layer Stack Up Detail for: TIDA-01063_E1" at 9372,4184.1 h57
  text "Layer" at 9372,4112.4 h24
  text "Gerber" at 10267.81,4112.4 h24
  text "Copper" at 10831.33,4112.4 h24
  text "Dielectric" at 11434.04,4112.4 h24
  text "Name" at 9372,4064.4 h24
  text "Document" at 10267.81,4064.4 h24
  text "Thickness" at 10831.33,4064.4 h24
  text "Material" at 11434.04,4064.4 h24
  text "Top Solder Mask" at 9372,3971.44 h34
  text "(.GTS)" at 10267.81,3971.44 h34
  text "Solder Resist" at 11434.04,3971.44 h34
  text "Top Layer" at 9372,3874.69 h34
  text "(.GTL)" at 10267.81,3874.69 h34
  text "1.4mil" at 10831.33,3874.69 h34
  text "FR-4 High Tg" at 11463,3874 h34
  text "FR-4 High Tg" at 11465,3655 h34
  text "Bottom Layer" at 9378,3645 h34
  text "(.GBL)" at 10276,3644 h34
  text "1.4mil" at 10836,3638 h34
  text "Solder Resist" at 11428,3571 h34
  text "(.GBS)" at 10273,3564 h34
  text "Bottom Solder Mask" at 9375,3559 h34
M13 Component Bodies Top:
  text ".Layer_Name" at -1381,-4374.49 h60
M14 Component Bodies Bottom:
  text ".Layer_Name" at -1381,-4374.49 h60
M15 Courtyards Top:
  text ".Layer_Name" at -1381,-4374.49 h60
M16 Courtyards Bottom:
  text ".Layer_Name" at -1381,-4374.49 h60
Drill Drawing:
  text ".legend" at 2724.9,1038.18 h60
  text "Drill Table" at 2721.9,867.18 h60
  text "FOR 16MIL DRILL +0/-16MIL" at 2749.9,661.18 h60
  text "FOR PTH DRILL +/-3MIL" at 2756.18,555.08 h60
  text ".Layer_Name" at -1381,-4374.49 h60

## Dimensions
1968.5,0 to 0,0 on M2 Board Dimensions
-1958,-3916 to -958,-3916 on M2 Board Dimensions
0,0 to 0,1968.5 on M2 Board Dimensions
